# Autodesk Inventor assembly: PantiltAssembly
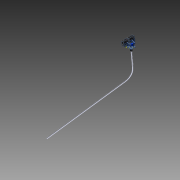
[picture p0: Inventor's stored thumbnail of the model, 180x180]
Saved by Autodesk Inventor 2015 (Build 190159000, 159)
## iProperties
Created: 2015-02
Part Number: PantiltAssembly
Document SubType Name: Assembly
Designer: sungeun
Author: sungeun
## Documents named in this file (14)
- \\psf\Google Drive\FabAcademy2015 archive\2.ComputerAidDesign\3d model files\Pantilt\PantiltAssembly.iam
- \\psf\Google Drive\FabAcademy2015 archive\2.ComputerAidDesign\3d model files\Boopidoo Inventor Parts (Servos & Rx)\servo_hxt900.ipt
- \\psf\Google Drive\FabAcademy2015 archive\2.ComputerAidDesign\3d model files\Pantilt\panTiltScaled.ipt
- \\psf\Google Drive\FabAcademy2015 archive\2.ComputerAidDesign\3d model files\Boopidoo Inventor Parts (Servos & Rx)\servo_hxt900_arm-4A.ipt
- \\psf\Google Drive\FabAcademy2015 archive\2.ComputerAidDesign\3d model files\Pantilt\panTiltBaseScaled.ipt
- \\psf\Google Drive\FabAcademy2015 archive\2.ComputerAidDesign\3d model files\Pantilt\vertMountScaled.ipt
- \\psf\Google Drive\FabAcademy2015 archive\2.ComputerAidDesign\3d model files\Pantilt\bracketScaled.ipt
- \\psf\Google Drive\FabAcademy2015 archive\2.ComputerAidDesign\3d model files\Boopidoo Inventor Parts (Servos & Rx)\servo_hxt900_arm-1A.ipt
- \\psf\Google Drive\FabAcademy2015 archive\2.ComputerAidDesign\3d model files\gopro--2.snapshot.2\gopro-hero-3-hd-camera.snapshot.2\GoPro Hero 3 HD Camera\GoPro Hero 3 HD Camera.iam
- \\psf\Google Drive\FabAcademy2015 archive\2.ComputerAidDesign\3d model files\Pantilt\goPro3dMountScaled.ipt
- \\psf\Google Drive\FabAcademy2015 archive\2.ComputerAidDesign\3d model files\Pantilt\goproCase.ipt
- \\psf\Google Drive\FabAcademy2015 archive\2.ComputerAidDesign\3d model files\Pantilt\balljointup.ipt
- \\psf\Google Drive\FabAcademy2015 archive\2.ComputerAidDesign\3d model files\Pantilt\balljointdown.ipt
- \\psf\Google Drive\FabAcademy2015 archive\2.ComputerAidDesign\3d model files\Pantilt\aluminium pipe.ipt
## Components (16 placed, 13 different names)
1. servo_hxt900:1 — Angle:1, Mate:1, Mate:2, Mate:3, Mate:4, Mate:5, Angle:5
2. panTiltScaled:1 — Angle:1, Mate:1, Mate:2, Mate:3, Flush:1, Mate:8, Mate:9, Flush:2, Mate:12, Mate:13
3. servo_hxt900_arm-4A:1 — Mate:4, Mate:5, Mate:10, Mate:11, Angle:2, Mate:30, Angle:5
4. panTiltBaseScaled:1 — Mate:10, Mate:11, Angle:2, Mate:31
5. vertMountScaled:1 — Flush:1, Mate:8, Mate:9, Mate:15, Flush:3, Mate:19
6. bracketScaled:1 — Flush:2, Mate:12, Mate:13, Flush:4
7. servo_hxt900:2 — Mate:15, Flush:3, Mate:17, Mate:19, Mate:35, Angle:4
8. servo_hxt900_arm-1A:1 — Mate:17, Mate:18, Angle:3, Angle:4
9. GoPro Hero 3 HD Camera:1 [sub-assembly] — Mate:24, Mate:25, Mate:26
10. goPro3dMountScaled:1 — Mate:18, Flush:4, Angle:3, Mate:21, Flush:5, Flush:8, Mate:23, Mate:35
11. goproCase:1 — Mate:21, Flush:5, Mate:22, Flush:7, Mate:24, Mate:25, Mate:26
12. goproCase:2 — Mate:22, Flush:7, Flush:8, Mate:23, Mate:27, Mate:28, Mate:29
13. GoPro Hero 3 HD Camera:2 [sub-assembly] — Mate:27, Mate:28, Mate:29
14. balljointup:1 — Mate:30, Mate:31, Mate:32
15. balljointdown:1 — Mate:32, Mate:33, Mate:34
16. aluminium pipe:1 — Mate:33, Mate:34
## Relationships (42: Mate 30, Flush 7, Angle 5)
- Angle:1: servo_hxt900:1 ↔ panTiltScaled:1
- Mate:1: servo_hxt900:1 ↔ panTiltScaled:1
- Mate:2: servo_hxt900:1 ↔ panTiltScaled:1
- Mate:3: servo_hxt900:1 ↔ panTiltScaled:1
- Mate:4: servo_hxt900:1 ↔ servo_hxt900_arm-4A:1
- Mate:5: servo_hxt900:1 ↔ servo_hxt900_arm-4A:1
- Flush:1: panTiltScaled:1 ↔ vertMountScaled:1
- Mate:8: panTiltScaled:1 ↔ vertMountScaled:1
- Mate:9: panTiltScaled:1 ↔ vertMountScaled:1
- Mate:10: servo_hxt900_arm-4A:1 ↔ panTiltBaseScaled:1
- Mate:11: servo_hxt900_arm-4A:1 ↔ panTiltBaseScaled:1
- Angle:2: servo_hxt900_arm-4A:1 ↔ panTiltBaseScaled:1
- Flush:2: panTiltScaled:1 ↔ bracketScaled:1
- Mate:12: panTiltScaled:1 ↔ bracketScaled:1
- Mate:13: panTiltScaled:1 ↔ bracketScaled:1
- Mate:15: vertMountScaled:1 ↔ servo_hxt900:2
- Flush:3: vertMountScaled:1 ↔ servo_hxt900:2
- Mate:17: servo_hxt900:2 ↔ servo_hxt900_arm-1A:1
- Mate:18: servo_hxt900_arm-1A:1 ↔ goPro3dMountScaled:1
- Flush:4: bracketScaled:1 ↔ goPro3dMountScaled:1
- Mate:19: vertMountScaled:1 ↔ servo_hxt900:2
- Angle:3: servo_hxt900_arm-1A:1 ↔ goPro3dMountScaled:1
- Mate:21: goPro3dMountScaled:1 ↔ goproCase:1
- Flush:5: goPro3dMountScaled:1 ↔ goproCase:1
- Mate:22: goproCase:1 ↔ goproCase:2
- Flush:7: goproCase:1 ↔ goproCase:2
- Flush:8: goPro3dMountScaled:1 ↔ goproCase:2
- Mate:23: goPro3dMountScaled:1 ↔ goproCase:2
- Mate:24: GoPro Hero 3 HD Camera:1 ↔ goproCase:1
- Mate:25: GoPro Hero 3 HD Camera:1 ↔ goproCase:1
- Mate:26: GoPro Hero 3 HD Camera:1 ↔ goproCase:1
- Mate:27: goproCase:2 ↔ GoPro Hero 3 HD Camera:2
- Mate:28: goproCase:2 ↔ GoPro Hero 3 HD Camera:2
- Mate:29: goproCase:2 ↔ GoPro Hero 3 HD Camera:2
- Mate:30: servo_hxt900_arm-4A:1 ↔ balljointup:1
- Mate:31: panTiltBaseScaled:1 ↔ balljointup:1
- Mate:32: balljointup:1 ↔ balljointdown:1
- Mate:33: balljointdown:1 ↔ aluminium pipe:1
- Mate:34: balljointdown:1 ↔ aluminium pipe:1
- Mate:35: servo_hxt900:2 ↔ goPro3dMountScaled:1
- Angle:4: servo_hxt900:2 ↔ servo_hxt900_arm-1A:1
- Angle:5: servo_hxt900:1 ↔ servo_hxt900_arm-4A:1
